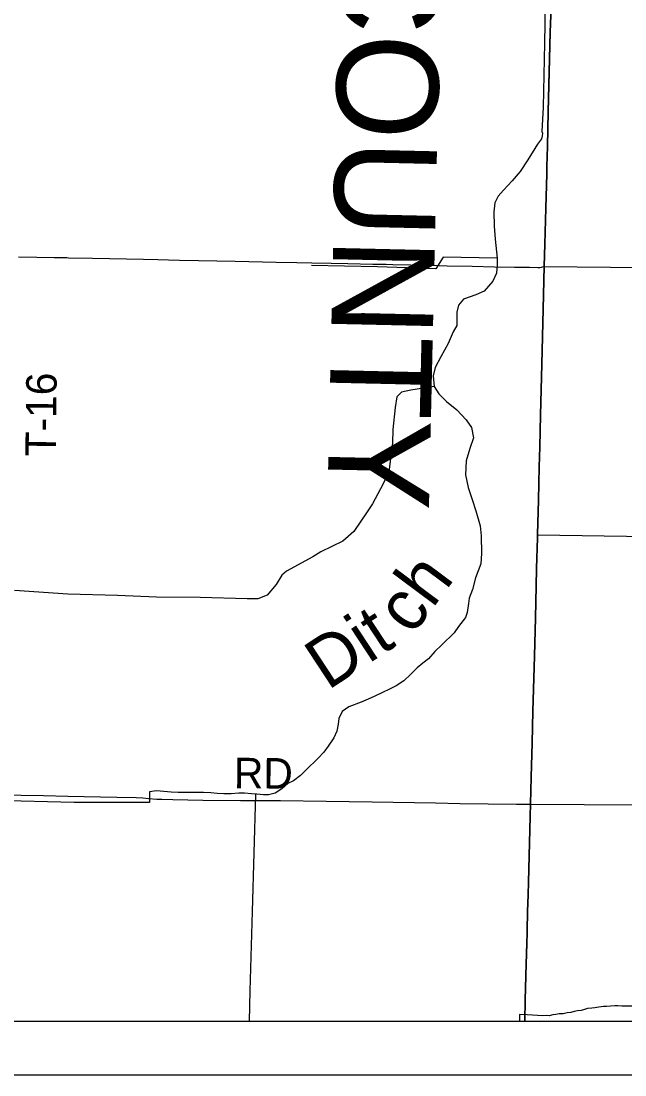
# Model space of a CAD drawing. Extents: x 0 to 34, y 0 to 22.
# Drawn here: x 6.077 to 7.202, y 14 to 15.963 of the extents above; entities that cross this region are included whole.
import ezdxf

# ---------------------------------------------------------------- set-up
doc = ezdxf.new("R2010")
doc.units = 0
for name, color, linetype in [('Default', 7, 'Continuous'), ('GM_X_County_Road', 7, 'Continuous'), ('GM_X_County_Text', 7, 'Continuous'), ('GM_X_Minor_River', 7, 'Continuous'), ('GM_X_Minor_River_Text', 7, 'Continuous'), ('GM_X_State_Route', 7, 'Continuous'), ('GM_X_Township_Road', 7, 'Continuous'), ('GM_X_Township_Road_Text', 7, 'Continuous'), ('GM_X_US_Route', 7, 'Continuous'), ('SH_Cut_Line', 7, 'Continuous'), ('SH_Data', 7, 'Continuous')]:
    doc.layers.add(name, color=color, linetype=linetype)

msp = doc.modelspace()

# ---------------------------------------------------------------- linework, layer by layer
at = {"layer": 'Default'}
for points in [[(2.1, 14.1), (7.0155, 14.1), (7.0165, 14.1397), (7.0184, 14.2065), (7.0196, 14.2454), (7.0201, 14.264), (7.02, 14.2765), (7.0201, 14.2796), (7.0205, 14.2936), (7.0205, 14.2967), (7.0207, 14.3029), (7.0206, 14.3044), (7.0217, 14.3355), (7.0225, 14.3588), (7.0256, 14.4816), (7.0263, 14.505), (7.0278, 14.5546), (7.0293, 14.6183), (7.0307, 14.6774), (7.0335, 14.7799), (7.0355, 14.8514), (7.0367, 14.9104), (7.0376, 14.9431), (7.0392, 15.0006), (7.0394, 15.0065), (7.041, 15.0705), (7.0424, 15.1327), (7.0435, 15.1699), (7.0449, 15.229), (7.0473, 15.3238), (7.0498, 15.4263), (7.0517, 15.5064), (7.0529, 15.5475), (7.0548, 15.6144), (7.0566, 15.6781), (7.0568, 15.6921), (7.0579, 15.7293), (7.0595, 15.7946), (7.0632, 15.9422), (7.0646, 15.9888)], [(7.0646, 15.9888), (7.0632, 15.9422), (7.0595, 15.7946), (7.0579, 15.7293), (7.0568, 15.6921), (7.0566, 15.6781), (7.0548, 15.6144), (7.0529, 15.5475), (7.0517, 15.5064), (7.0498, 15.4263), (7.0473, 15.3238), (7.0449, 15.229), (7.0435, 15.1699), (7.0424, 15.1327), (7.041, 15.0705), (7.0394, 15.0065), (7.0392, 15.0006), (7.0376, 14.9431), (7.0367, 14.9104), (7.0355, 14.8514), (7.0335, 14.7799), (7.0307, 14.6774), (7.0293, 14.6183), (7.0278, 14.5546), (7.0263, 14.505), (7.0256, 14.4816), (7.0225, 14.3588), (7.0217, 14.3355), (7.0206, 14.3044), (7.0207, 14.3029), (7.0205, 14.2967), (7.0205, 14.2936), (7.0201, 14.2796), (7.02, 14.2765), (7.0201, 14.264), (7.0196, 14.2454), (7.0184, 14.2065), (7.0165, 14.1397), (7.0155, 14.1), (8.9, 14.1)]]:
    msp.add_lwpolyline(points, dxfattribs=at)
at = {"layer": 'GM_X_County_Road'}
msp.add_lwpolyline([(7.0265, 14.5045), (7.5252, 14.501), (8.0219, 14.4983), (8.9, 14.4934)], dxfattribs=at)
at = {"layer": 'GM_X_Minor_River'}
for points in [[(7.0545, 16.0319), (7.0522, 15.9219), (7.0496, 15.8024), (7.0477, 15.7573), (7.0484, 15.7542), (7.0483, 15.7489), (7.047, 15.7437), (7.0392, 15.7336), (7.0211, 15.7044), (7.0069, 15.6828), (6.9921, 15.6653), (6.9757, 15.6482), (6.966, 15.6367), (6.96, 15.6243), (6.9581, 15.6077), (6.9589, 15.5811), (6.9606, 15.5567), (6.9643, 15.5214), (6.9639, 15.5088), (6.9628, 15.4933), (6.9564, 15.4783), (6.94, 15.4597), (6.9247, 15.4532), (6.9018, 15.4451), (6.892, 15.4335), (6.889, 15.4207), (6.8892, 15.396), (6.8821, 15.3841), (6.8732, 15.3623), (6.8593, 15.3376), (6.8486, 15.3177), (6.8452, 15.3018), (6.847, 15.2824), (6.8557, 15.2686), (6.8701, 15.2542), (6.8891, 15.2385), (6.9064, 15.2203), (6.9167, 15.2056), (6.92, 15.1866), (6.9134, 15.1666), (6.9064, 15.1436), (6.905, 15.1178), (6.9101, 15.0938), (6.9175, 15.0716), (6.9246, 15.0506), (6.9326, 15.0227), (6.9344, 15.004), (6.9351, 14.971), (6.9335, 14.9521), (6.9241, 14.9257), (6.9183, 14.9042), (6.9122, 14.8881), (6.9108, 14.8778), (6.9081, 14.8612), (6.9052, 14.8518), (6.8923, 14.8354)], [(6.9643, 15.5214), (6.8639, 15.523), (6.8501, 15.5014), (6.7416, 15.5051), (6.6182, 15.5074)], [(6.847, 15.2824), (6.8033, 15.2755), (6.7857, 15.2714), (6.7776, 15.2629), (6.7741, 15.2432), (6.77, 15.2023), (6.769, 15.1769), (6.7656, 15.1478), (6.7624, 15.1228), (6.752, 15.1011), (6.7321, 15.0636), (6.7219, 15.0487), (6.6971, 15.0121), (6.677, 14.9943), (6.636, 14.9745), (6.621, 14.965), (6.5715, 14.9381), (6.563, 14.9307), (6.5523, 14.9135), (6.5359, 14.8934), (6.5187, 14.8866), (6.4983, 14.8867), (6.4108, 14.8892), (6.3298, 14.89), (6.2572, 14.893), (6.1645, 14.8956), (6.065, 14.9022)], [(6.8923, 14.8354), (6.8843, 14.8234), (6.8609, 14.8013), (6.8484, 14.7884), (6.8362, 14.7747), (6.8257, 14.767), (6.8152, 14.7582), (6.8031, 14.7464), (6.7906, 14.7342), (6.7762, 14.7248), (6.7635, 14.7187), (6.7504, 14.7122), (6.7365, 14.7054), (6.7242, 14.6997), (6.7111, 14.694), (6.6881, 14.6855), (6.6753, 14.6768), (6.6692, 14.6637), (6.6678, 14.6531), (6.6655, 14.6402), (6.6602, 14.6278), (6.6491, 14.6122), (6.6412, 14.6014), (6.631, 14.5899), (6.6075, 14.5678), (6.5978, 14.5579), (6.5846, 14.548), (6.5745, 14.5426), (6.5632, 14.5326), (6.5508, 14.525), (6.5382, 14.5216), (6.5287, 14.5219), (6.5166, 14.5226), (6.5063, 14.5233), (6.4935, 14.5248), (6.4832, 14.5247), (6.4687, 14.5236), (6.455, 14.5236), (6.4425, 14.5244), (6.4308, 14.5255), (6.4171, 14.5263), (6.4034, 14.5259), (6.392, 14.5259), (6.3825, 14.5258), (6.37, 14.5257), (6.3567, 14.5269), (6.3434, 14.5277), (6.3294, 14.5288), (6.3168, 14.5272)], [(6.3168, 14.5272), (6.3166, 14.5075), (6.1764, 14.5075), (6.0272, 14.5114), (6.0217, 14.3475), (6.0152, 14.1)], [(6.5139, 14.5228), (6.508, 14.3044), (6.5033, 14.1564), (6.5022, 14.1)], [(7.2163, 14.1283), (7.1965, 14.1283), (7.1889, 14.1287), (7.1832, 14.1284), (7.1756, 14.128), (7.1677, 14.1276), (7.1623, 14.1272), (7.1536, 14.1261), (7.1464, 14.1249), (7.1403, 14.1246), (7.1327, 14.1234), (7.127, 14.1219), (7.1205, 14.12), (7.1137, 14.1196), (7.1076, 14.1181), (7.1015, 14.1162), (7.0947, 14.1154), (7.0871, 14.1139), (7.0795, 14.1135), (7.0734, 14.1128), (7.0677, 14.112), (7.0613, 14.1101), (7.0559, 14.1105), (7.0495, 14.1101), (7.02, 14.1117)], [(7.02, 14.1117), (7.0059, 14.1125), (7.0055, 14.1)]]:
    msp.add_lwpolyline(points, dxfattribs=at)
at = {"layer": 'GM_X_State_Route'}
msp.add_lwpolyline([(7.0519, 15.5059), (8.039, 15.4956), (8.9, 15.4867)], dxfattribs=at)
at = {"layer": 'GM_X_Township_Road'}
msp.add_line((7.0396, 15.006), (8.0249, 14.9917), dxfattribs=at)
for points in [[(6.0724, 15.5237), (6.1066, 15.5232), (6.1393, 15.5227), (6.1626, 15.5222), (6.1657, 15.5221), (6.2107, 15.5213), (6.2418, 15.5206), (6.3055, 15.5193), (6.3319, 15.5186), (6.3521, 15.518), (6.3723, 15.5175), (6.408, 15.5166), (6.4421, 15.516), (6.4763, 15.5155), (6.5524, 15.5141), (6.5913, 15.5132), (6.6192, 15.5128), (6.655, 15.5119), (6.686, 15.5113), (6.7326, 15.5103), (6.7575, 15.5099), (6.7699, 15.5097), (6.8026, 15.5089), (6.8414, 15.508), (6.8709, 15.5072), (6.9175, 15.5061), (6.9594, 15.5052), (6.9967, 15.5046), (7.0247, 15.5043), (7.0402, 15.504), (7.0434, 15.5041), (7.0465, 15.5044), (7.0489, 15.505), (7.0519, 15.5059)], [(6.0463, 14.5219), (6.0774, 14.5212), (6.1193, 14.5202), (6.1644, 14.5193), (6.256, 14.5174), (6.2917, 14.5166), (6.3041, 14.516), (6.315, 14.5151), (6.3305, 14.5138), (6.3398, 14.5133), (6.36, 14.513), (6.4159, 14.512), (6.4859, 14.5109), (6.5061, 14.5109), (6.5216, 14.5114), (6.5325, 14.5114), (6.5604, 14.511), (6.6459, 14.5097), (6.7313, 14.5084), (6.8494, 14.5065), (6.8945, 14.5057), (7.0001, 14.5044), (7.0188, 14.5044), (7.0265, 14.5045)]]:
    msp.add_lwpolyline(points, dxfattribs=at)
at = {"layer": 'GM_X_US_Route'}
msp.add_lwpolyline([(7.0158, 14.1), (7.0167, 14.1392), (7.0186, 14.206), (7.0198, 14.2448), (7.0203, 14.2635), (7.0203, 14.2759), (7.0203, 14.279), (7.0207, 14.293), (7.0207, 14.2961), (7.0209, 14.3023), (7.0208, 14.3039), (7.022, 14.3349), (7.0228, 14.3583), (7.0258, 14.481), (7.0265, 14.5045), (7.028, 14.554), (7.0295, 14.6178), (7.0309, 14.6768), (7.0337, 14.7794), (7.0357, 14.8508), (7.037, 14.9099), (7.0379, 14.9425), (7.0395, 15), (7.0396, 15.006), (7.0412, 15.0699), (7.0426, 15.1321), (7.0437, 15.1694), (7.0452, 15.2284), (7.0476, 15.3232), (7.05, 15.4258), (7.0519, 15.5059), (7.0532, 15.547), (7.055, 15.6138), (7.0568, 15.6775), (7.057, 15.6915), (7.0581, 15.7288), (7.0597, 15.7941), (7.0634, 15.9417), (7.0648, 15.9883)], dxfattribs=at)
at = {"layer": 'SH_Cut_Line'}
for points in [[(2.1, 14.1), (7.0155, 14.1), (7.0165, 14.1397), (7.0184, 14.2065), (7.0196, 14.2454), (7.0201, 14.264), (7.02, 14.2765), (7.0201, 14.2796), (7.0205, 14.2936), (7.0205, 14.2967), (7.0207, 14.3029), (7.0206, 14.3044), (7.0217, 14.3355), (7.0225, 14.3588), (7.0256, 14.4816), (7.0263, 14.505), (7.0278, 14.5546), (7.0293, 14.6183), (7.0307, 14.6774), (7.0335, 14.7799), (7.0355, 14.8514), (7.0367, 14.9104), (7.0376, 14.9431), (7.0392, 15.0006), (7.0394, 15.0065), (7.041, 15.0705), (7.0424, 15.1327), (7.0435, 15.1699), (7.0449, 15.229), (7.0473, 15.3238), (7.0498, 15.4263), (7.0517, 15.5064), (7.0529, 15.5475), (7.0548, 15.6144), (7.0566, 15.6781), (7.0568, 15.6921), (7.0579, 15.7293), (7.0595, 15.7946), (7.0632, 15.9422), (7.0646, 15.9888)], [(7.0646, 15.9888), (7.0632, 15.9422), (7.0595, 15.7946), (7.0579, 15.7293), (7.0568, 15.6921), (7.0566, 15.6781), (7.0548, 15.6144), (7.0529, 15.5475), (7.0517, 15.5064), (7.0498, 15.4263), (7.0473, 15.3238), (7.0449, 15.229), (7.0435, 15.1699), (7.0424, 15.1327), (7.041, 15.0705), (7.0394, 15.0065), (7.0392, 15.0006), (7.0376, 14.9431), (7.0367, 14.9104), (7.0355, 14.8514), (7.0335, 14.7799), (7.0307, 14.6774), (7.0293, 14.6183), (7.0278, 14.5546), (7.0263, 14.505), (7.0256, 14.4816), (7.0225, 14.3588), (7.0217, 14.3355), (7.0206, 14.3044), (7.0207, 14.3029), (7.0205, 14.2967), (7.0205, 14.2936), (7.0201, 14.2796), (7.02, 14.2765), (7.0201, 14.264), (7.0196, 14.2454), (7.0184, 14.2065), (7.0165, 14.1397), (7.0155, 14.1), (8.9, 14.1)]]:
    msp.add_lwpolyline(points, dxfattribs=at)
at = {"layer": 'SH_Data'}
for p, q in [((2.1, 14.1), (8.9, 14.1)), ((2, 14), (9, 14))]:
    msp.add_line(p, q, dxfattribs=at)

# ---------------------------------------------------------------- texts
at = {"layer": 'GM_X_County_Text'}
msp.add_text('WOOD COUNTY', height=0.189394, rotation=268.7124, dxfattribs=at).set_placement((6.6916, 17.0099))
at = {"layer": 'GM_X_Minor_River_Text'}
for s, height, rotation, p in [('ch', 0.09476, 53.3151, (6.8059, 14.8168)), ('Dit', 0.09475, 33.3141, (6.6485, 14.7152))]:
    msp.add_text(s, height=height, rotation=rotation, dxfattribs=at).set_placement(p)
at = {"layer": 'GM_X_Township_Road_Text'}
for s, rotation, p in [('T-16', 89.2959, (6.142, 15.1516)), ('RD', 359.5129, (6.4736, 14.534))]:
    msp.add_text(s, height=0.05682, rotation=rotation, dxfattribs=at).set_placement(p)

doc.saveas('drawing.dxf')
